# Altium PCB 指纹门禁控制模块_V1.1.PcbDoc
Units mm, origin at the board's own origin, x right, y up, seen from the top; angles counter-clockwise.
Board outline 60 x 20 mm, 2 copper layers (Top Layer, Bottom Layer); 41 components, 29 nets, 157 pads, 102 vias.
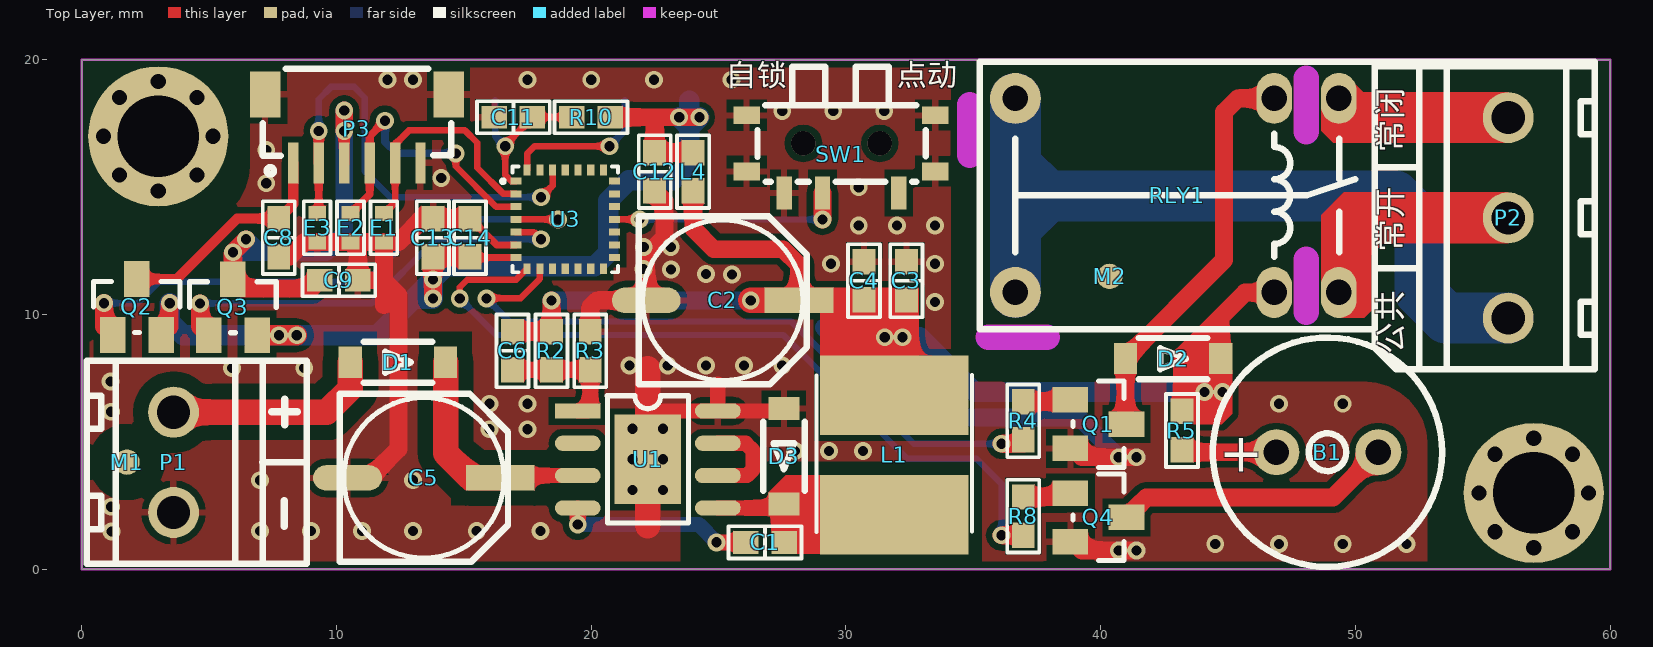
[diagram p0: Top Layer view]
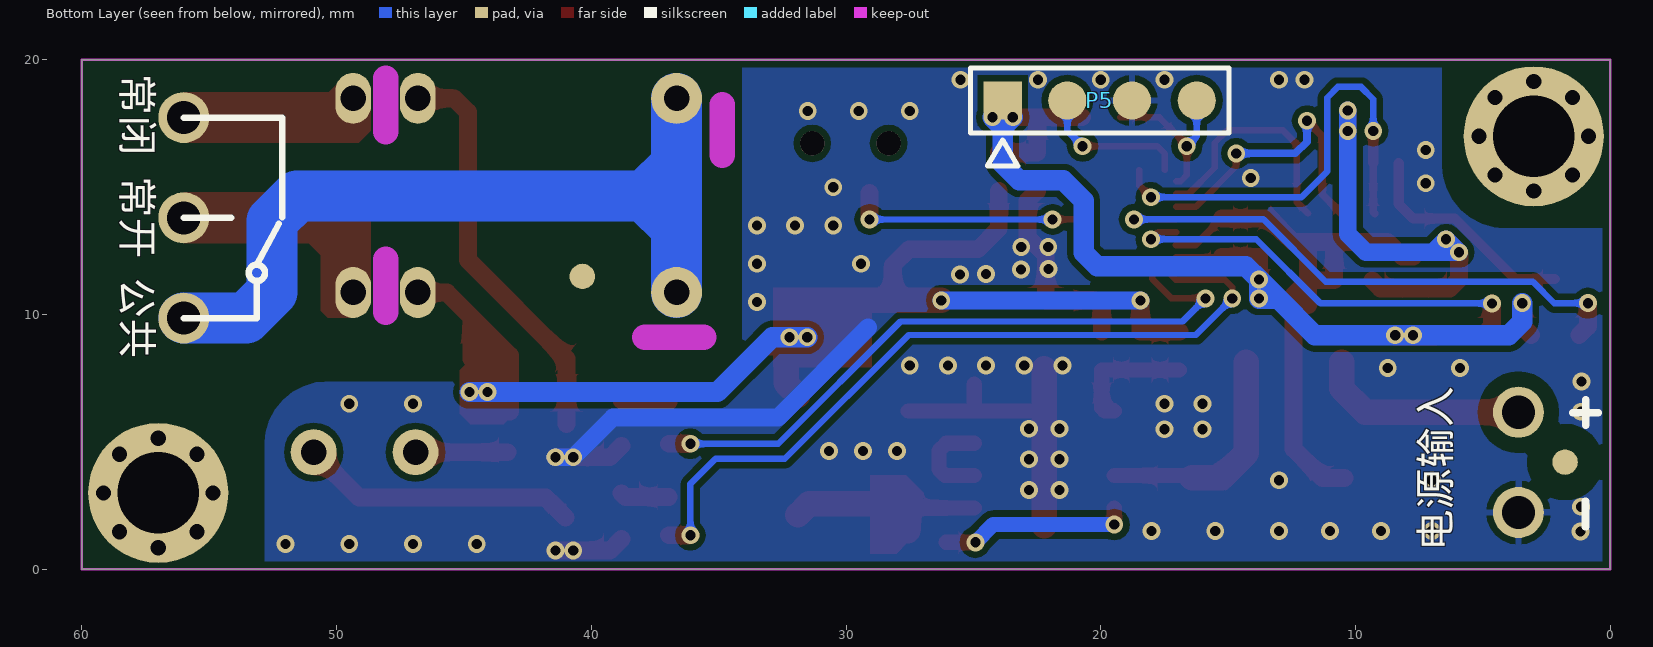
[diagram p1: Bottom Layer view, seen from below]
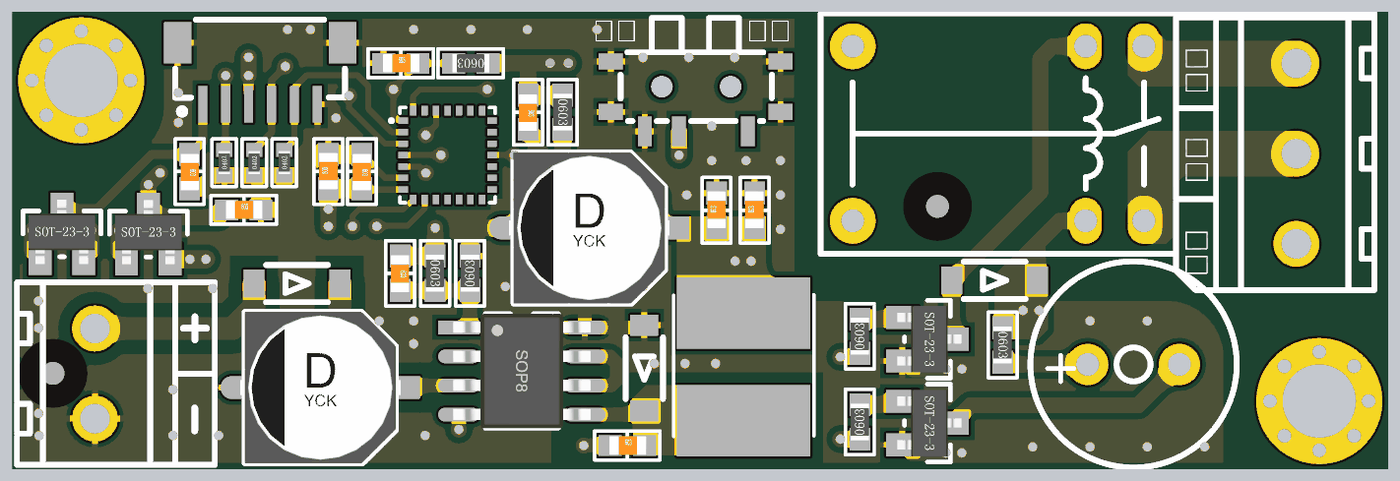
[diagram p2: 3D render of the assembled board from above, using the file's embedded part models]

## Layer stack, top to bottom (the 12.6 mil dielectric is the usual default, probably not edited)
Top Solder: solder mask 0.0102, Solder Resist, Dk 3.5
Top Layer: signal copper 0.0356
Dielectric 1: dielectric 0.32, FR-4, Dk 4.8
Bottom Layer: signal copper 0.0356
Bottom Solder: solder mask 0.0102, Solder Resist, Dk 3.5

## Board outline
0,0 60,0 60,20 0,20

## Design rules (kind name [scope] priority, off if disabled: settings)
Clearance Clearance_2 [InComponent('U3')] p1: gap=0.2
Clearance Clearance_1 [InNet('NetD1_1') Or InNet('VIN') vs InPolygon] p2: gap=0.6
Clearance [All] p3: gap=0.254
ComponentClearance [All] p1: gap=0 collisioncheckmode=3 verticalgap=0 showdistances=FALSE
HoleSize [All] p1 off: absolutevalues=TRUE maxlimit=2.54 minlimit=0.025 maxpercent=80.000 minpercent=20.000
HoleToHoleClearance [All] p1 off: gap=0.254 allowstackedmicrovias=TRUE
LayerPairs [All] p1 off: enforce=TRUE
MinimumSolderMaskSliver [All] p1 off: minsoldermaskwidth=0.254
NetAntennae [All] p1 off: netantennaetolerance=0
PolygonConnect PolygonConnect_1 [InNet('GND') And isvia] p1: connectstyle=Direct reliefconductorwidth=0.254 reliefentries=4 polygonreliefangle="90 Angle" airgapwidth=0.254
PolygonConnect [All] p2: connectstyle=Relief reliefconductorwidth=0.254 reliefentries=4 polygonreliefangle="90 Angle" airgapwidth=0.254
RoutingVias [All] p1: holewidth=0.711 width=1.27 viastyle="Through Hole" minholewidth=0.1 minwidth=0.1 maxholewidth=0.711 maxwidth=1.27
SilkToBoardRegionClearance [All] p1 off:
SilkToSilkClearance [All] p1 off: silktosilkclearance=0.254
SilkToSolderMaskClearance [IsPad] p1 off: minsilkscreentomaskgap=0.254 clearancetoexposedcopper=TRUE
SolderMaskExpansion [All] p1: expansion=0.102
Width [All] p1: maxlimit=8 minlimit=0.254 preferedwidth=0.254
21 further rules are at their usual default settings.

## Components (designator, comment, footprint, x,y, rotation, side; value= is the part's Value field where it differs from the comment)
B1 "QMB-09B-03" BUZZER-9MM 48.9,4.6 r0 top
C1 "104 100V 10% X7R 0603" C0603 26.82,1.06 r0 top
C2 "220uF 6.3V 贴片电解电容" CAP-D6.3XH7.7 25.16,10.56 r0 top
C3 "10uF 10V 20% X5R 0603" C0603 32.37,11.33 r90 top
C4 "104 16V 10% X7R 0603" C0603 30.71,11.33 r90 top
C5 "10uF 100V 贴片电解电容" CAP-D6.3XH7.7 13.43,3.59 r0 top
C6 "104 16V 10% X7R 0603" C0603 16.91,8.58 r270 top
C8 "104 16V 10% X7R 0603" C0603 7.73,13.02 r270 top
C9 "104 16V 10% X7R 0603" C0603 10.09,11.35 r0 top
C11 "104 16V 10% X7R 0603" C0603 16.94,17.75 r0 top
C12 "10uF 10V 20% X5R 0603" C0603 22.49,15.61 r270 top
C13 "10uF 10V 20% X5R 0603" C0603 13.78,13.02 r90 top
C14 "104 16V 10% X7R 0603" C0603 15.24,13.02 r270 top
D1 "SOD1F3" SOD-123 12.41,8.13 r0 top
D2 "SOD1F3" SOD-123 42.84,8.27 r0 top
D3 "SOD1F3" SOD-123 27.56,4.44 r270 top
E1 "LXES15AAA1-153" R0402 11.86,13.41 r90 top
E2 "LXES15AAA1-153" R0402 10.55,13.41 r90 top
E3 "LXES15AAA1-153" R0402 9.24,13.41 r90 top
L1 "33uH" L-SMD-5.8X5.2 31.89,4.49 r90 top
L4 "120Ω @100MHz" R0603 24,15.61 r270 top
M1 "MARK" MARK 1.77,4.21 r0 top
M2 "MARK" MARK 40.35,11.5 r0 top
P1 "KF396-2 接线端子" KF396-2 3.6,4.2 r270 top
P2 "KF396-3 接线端子" KF396-3 56,13.8 r90 top
P3 "6P-1.0mm-立式贴片插座" "SH 1.0_LS_6P" 10.8,17.3 r0 top
P5 "STM8 烧写口" HDR1X4 23.85,18.408 r180 bottom
Q1 "S8050" SOT-23 39.91,5.7 r270 top
Q2 "SI2301" SOT-23 2.16,10.3 r0 top
Q3 "SI2301" SOT-23 5.93,10.29 r0 top
Q4 "S8050" SOT-23 39.91,2.04 r270 top
R2 "154K 1% 0603" R0603 18.435,8.58 r270 top
R3 "10K 1% 0603" R0603 19.96,8.58 r90 top
R4 "1K 1% 0603" R0603 36.96,5.83 r90 top
R5 "51R 1% 0603" R0603 43.19,5.45 r270 top
R8 "1K 1% 0603" R0603 36.96,2.09 r90 top
R10 "10K 1% 0603" R0603 19.99,17.75 r180 top
RLY1 "HK4100F-DC3V-SHG" RELAY-TH_HK4100F-XXX-XXXX 43,14.68 r180 top
SW1 "MSK12CO2-BDM" SW-SMD_MSK12CO2-BDM 29.8,16.3 r180 top
U1 "MP9486A" SOP-8E 22.22,4.315 r270 top
U3 "STM8L151G4U6" UFQFPN-28 18.98,13.74 r270 top

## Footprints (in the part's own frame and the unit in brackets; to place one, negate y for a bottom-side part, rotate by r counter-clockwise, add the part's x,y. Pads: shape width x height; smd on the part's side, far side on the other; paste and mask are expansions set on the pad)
BUZZER-9MM [mm]
  round 1.8 hole 1: 1(-2,0) 2(2,0)
  silkscreen extent -4.5,-4.5 4.5,4.5
C0603 [mm]
  rect 1x0.9 smd: 1(-0.75,0) 2(0.75,0)
  silkscreen extent -1.43,-0.63 1.43,0.63, body extent -0.78,-0.4 0.82,0.4, height 0.3
CAP-D6.3XH7.7 [mm] "贴片电解电容，直径6.3mm，高7.7mm"
  rect 2.7x1 smd: 1(3,0)
  oval 2.7x1 smd: 2(-3,0)
  silkscreen extent -3.3,-3.3 3.3,3.3, body extent -3.5,-3.3 3.5,3.3, height 7.7
HDR1X4 [mm] "Connector; Header; 4 Position"
  rect 1.5x1.5 smd: 1(0,0)
  round 1.5 smd: 2(2.54,0) 3(5.08,0) 4(7.62,0)
  silkscreen extent -1.27,-1.27 8.89,1.27
KF396-2 [mm]
  round 2 hole 1.3: 1(-1.968,0) 2(1.968,0)
  silkscreen extent -3.98,-3.4 3.98,3.5
KF396-3 [mm]
  round 2 hole 1.3: 1(-3.937,0) 2(0,0) 3(3.937,0)
  silkscreen extent -5.95,-3.4 5.95,3.5
L-SMD-5.8X5.2 [mm]
  rect 3.124x5.82 smd: 1(-2.351,0) 2(2.351,0)
  silkscreen extent -3.03,-3.06 3.15,3.05
MARK [mm] "MARK点，外径3mm，内径1mm"
  round 1 smd: 1(0,0)
  round 1 smd far side: 1(0,0)
  Top Layer pour cut-out: 0,1.5 0.074,1.5 0.294,1.478 0.577,1.393 0.837,1.253 1.066,1.066 1.253,0.837 1.393,0.577 1.478,0.294 1.5,0.074 1.5,0 1.5,0 1.5,0 1.5,-0.074 1.478,-0.294 1.393,-0.577 1.253,-0.837 1.066,-1.066 0.837,-1.253 0.577,-1.393 0.294,-1.478 0.074,-1.5 0,-1.5 0,-1.5 -0.074,-1.5 -0.294,-1.478 -0.577,-1.393 -0.837,-1.253 -1.066,-1.066 -1.253,-0.837 -1.393,-0.577 -1.478,-0.294 -1.5,-0.074 -1.5,0 -1.5,0 -1.5,0 -1.5,0.074 -1.478,0.294 -1.393,0.577 -1.253,0.837 -1.066,1.066 -0.837,1.253 -0.577,1.393 -0.294,1.478 -0.074,1.5 0,1.5
  Bottom Layer pour cut-out: 0,1.5 -0.074,1.5 -0.294,1.478 -0.577,1.393 -0.837,1.253 -1.066,1.066 -1.253,0.837 -1.393,0.577 -1.478,0.294 -1.5,0.074 -1.5,0 -1.5,0 -1.5,0 -1.5,-0.074 -1.478,-0.294 -1.393,-0.577 -1.253,-0.837 -1.066,-1.066 -0.837,-1.253 -0.577,-1.393 -0.294,-1.478 -0.074,-1.5 0,-1.5 0,-1.5 0.074,-1.5 0.294,-1.478 0.577,-1.393 0.837,-1.253 1.066,-1.066 1.253,-0.837 1.393,-0.577 1.478,-0.294 1.5,-0.074 1.5,0 1.5,0 1.5,0 1.5,0.074 1.478,0.294 1.393,0.577 1.253,0.837 1.066,1.066 0.837,1.253 0.577,1.393 0.294,1.478 0.074,1.5 0,1.5
R0402 [mm]
  rect 0.6x0.7 smd: 1(-0.56,0) 2(0.56,0)
  silkscreen extent -1.04,-0.52 1.04,0.53, body extent -0.5,-0.25 0.5,0.25, height 0.35
R0603 [mm]
  rect 1x0.9 smd: 1(-0.75,0) 2(0.75,0)
  silkscreen extent -1.43,-0.63 1.43,0.63, body extent -0.8,-0.4 0.8,0.4, height 0.45
RELAY-TH_HK4100F-XXX-XXXX [mm]
  oval 1.4x2 hole 1: 1(-6.35,3.81) 2(-6.35,-3.81) 3(-3.81,3.81) 4(-3.81,-3.81)
  round 2 hole 1: 5(6.35,3.81) 6(6.35,-3.81)
  silkscreen extent -7.75,-5.25 7.75,5.25
"SH 1.0_LS_6P" [mm] "立式，1mm间距插座"
  rect 1.2x1.8 smd: 0(-3.6,1.345) 0(3.6,1.345)
  rect 0.4x1.6 smd: 1(-2.5,-1.345) 2(-1.5,-1.345) 3(-0.5,-1.345) 4(0.5,-1.345) 5(1.5,-1.345) 6(2.5,-1.345)
  silkscreen extent -3.7,-1.8 3.7,2.35
SOD-123 [mm]
  rect 0.909x1.219 smd: 1(-1.87,0) 2(1.87,0)
  silkscreen extent -1.35,-0.81 1.35,0.81
SOP-8E [mm]
  rect 3.51x2.62 smd: 0(0,0)
  rect 0.6x1.8 smd: 1(-1.905,-2.75)
  oval 0.6x1.8 smd: 2(-0.635,-2.75) 3(0.635,-2.75) 4(1.905,-2.75) 5(1.905,2.75) 6(0.635,2.75) 7(-0.635,2.75) 8(-1.905,2.75)
  silkscreen extent -2.5,-1.59 2.5,1.59, body extent -2.5,-3 2.5,3, height 1.9
SOT-23 [mm]
  rect 1x1.4 smd: 1(-0.95,-1.1) 2(0.95,-1.1) 3(0,1.1)
  silkscreen extent -1.7,-1 1.7,1, body extent -1.45,-1.31 1.45,1.49, height 1.2
SW-SMD_MSK12CO2-BDM [mm]
  rect 0.6x1.3 smd: 1(2.225,1.525) 2(0.725,1.525) 3(-2.275,1.525)
  rect 1.05x0.7 smd: 4(-3.7,-1.525) 4(-3.7,0.675) 4(3.7,0.675) 4(3.7,-1.525)
  round 0.95 hole 0.95 unplated: ""(-1.525,-0.425) ""(1.475,-0.425)
  silkscreen extent -3.33,-3.42 3.27,1.08
UFQFPN-28 [mm]
  rect 0.28x0.425 smd: 1(-1.5,-1.938) 2(-1,-1.938) 3(-0.5,-1.938) 4(0,-1.938) 5(0.5,-1.938) 6(1,-1.938) 7(1.5,-1.938) 15(1.5,1.938) 16(1,1.938) 17(0.5,1.938) 18(0,1.938) 19(-0.5,1.938) 20(-1,1.938) 21(-1.5,1.938)
  rect 0.425x0.28 smd: 8(1.938,-1.5) 9(1.938,-1) 10(1.938,-0.5) 11(1.938,0) 12(1.938,0.5) 13(1.938,1) 14(1.938,1.5) 22(-1.938,1.5) 23(-1.938,1) 24(-1.938,0.5) 25(-1.938,0) 26(-1.938,-0.5) 27(-1.938,-1) 28(-1.938,-1.5)
  silkscreen extent -2.08,-2.52 2.08,2.08

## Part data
C1 C3 C4 C6 C8 C9 C11 C12 C13 C14: library part CapN, "CAP"
C2 C5: library part CapH, "100uF,35V,插件电解电容"
D1 D2 D3: library part 1N4007
L1: library part InductorDM, "GCD54-330MC"
L4: library part Inductor, "CBW160808U121T"
P1: library part "Header 2", "Header, 2-Pin"
P2: library part "Header 3", "Header, 3-Pin"
P3: library part "Header 6", "Header, 6-Pin"
P5: library part "Header 4", "Header, 4-Pin"
Q1 Q4: library part NPN, "NPN晶体管"
Q2 Q3: library part MOSFET-P
R2 R3 R4 R5 R8 R10: library part Res1, "Resistor"
U1: "100V 输入，3.5A 峰值电流限 降压转换器"

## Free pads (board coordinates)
  round 0.7 hole 0.6: 0(0.85,17) 0(1.48,15.48) 0(1.48,18.52) 0(3,14.85) 0(3,19.15) 0(4.52,15.48) 0(4.52,18.52) 0(5.15,17) 0(54.85,3) 0(55.48,1.48) 0(55.48,4.52) 0(57,0.85) 0(57,5.15) 0(58.52,1.48) 0(58.52,4.52) 0(59.15,3)
  round 5.5 hole 3.2: 0(3,17) 0(57,3)

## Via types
v1: diameter 0.7, hole 0.4, Top Layer to Bottom Layer, tented both sides, 102 vias

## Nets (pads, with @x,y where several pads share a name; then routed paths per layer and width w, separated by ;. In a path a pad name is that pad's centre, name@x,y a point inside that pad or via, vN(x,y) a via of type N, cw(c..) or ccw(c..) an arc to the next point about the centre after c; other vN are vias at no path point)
3V3: C2.1 C3.1 C4.1 C6.1 D2.2 L1.2 L4.2 R2.1 R5.1 RLY1.3 | length 52.5
  Top Layer w0.7: C6.1 R2.1 18.44,9.335 v1(18.44,10.56) ; L4.2 24,13.38 24.81,12.57 27.53,12.57 28.16,11.94 C2.1 ; R5.1 43.19,7.99 ; RLY1.3 45.67,10.87 44.71,9.91 ; 43.19,7.99 43.19,8.39 44.71,9.91 ; 43.19,7.99 43.47,8.27 D2.2 44.71,9.91
  Top Layer w1: v1(26.26,10.56) C2.1 32.35,10.56 32.35,7.301 L1.2
  Bottom Layer w0.7: v1(18.44,10.56) v1(26.26,10.56)
  Bottom Layer w0.8: v1(31.52,9.11) 32.9,9.11 35.05,6.96 v1(44.08,6.96) v1(44.78,6.96)
  other v1: 32.22,9.11
BEEP: R8.1 U3.8 | length 30.5
  Top Layer w0.254: v1@14.835,10.65 14.835,11.075 15.13,11.37 17.048,11.37 U3.8
  Top Layer w0.7: v1(36.11,1.34) R8.1
  Bottom Layer w0.254: v1(14.835,10.63) 16.265,9.2 27.54,9.2 32.4,4.34 35.12,4.34 36.11,3.35 v1(36.11,1.34)
F_INT: E3.2 P3.2 U3.26 | length 18.2
  Top Layer w0.254: v1(18.03,14.61) 18.48,15.06 U3.26
  Top Layer w0.3: E3.2 9.3,14.03 P3.2
  Top Layer w0.4: P3.2 v1(9.3,17.21)
  Bottom Layer w0.254: v1(9.3,17.21) 9.3,18.46 9.78,18.94 10.69,18.94 11.11,18.52 11.11,15.62 12.12,14.61 v1(18.03,14.61)
F_RXD: E1.2 P3.5 U3.2 | length 9.5
  Top Layer w0.254: E1.2 12.3,14.41 P3.5 12.3,16.69 12.84,17.23 15.04,17.23 15.52,16.75 15.52,15.77 16.55,14.74 U3.2
F_TXD: E2.2 P3.4 U3.3 | length 11.5
  Top Layer w0.254: v1(14.68,16.33) 14.68,15.82 16.26,14.24 U3.3
  Top Layer w0.3: E2.2 11.3,14.72 P3.4 11.3,17.01 v1(11.9,17.61)
  Bottom Layer w0.3: v1(11.9,17.61) 11.9,16.79 12.36,16.33 v1(14.68,16.33)
FM_3V3: C9.1 P3.3 Q3.3 | length 18.5
  Top Layer w0.4: P3.3 v1(10.3,17.21)
  Top Layer w0.7: v1(6.44,12.96) v1(5.93,12.45) Q3.3 6.3,11.02 9.01,11.02 C9.1 ; v1(10.3,17.21) v1(10.3,18.01)
  Bottom Layer w0.7: v1(10.3,18.01) 10.3,13.17 9.58,12.45 6.95,12.45 ; 6.95,12.45 v1(5.93,12.45) v1(6.44,12.96) 6.95,12.45
FM_EN: Q3.1 U3.5 | length 16.9
  Top Layer w0.254: U3.5 17.75,13.24 v1(18.03,12.96)
  Top Layer w0.7: v1(4.64,10.44) 4.64,9.53 Q3.1
  Bottom Layer w0.254: v1(4.64,10.44) 11.37,10.44 13.89,12.96 v1(18.03,12.96)
FT_3V3: C8.1 P3.1 Q2.3 | length 9
  Top Layer w0.4: Q2.3 3.72,11.4 6.09,13.77 C8.1 8.3,14.34 P3.1
FT_EN: Q2.1 U3.4 | length 22.2
  Top Layer w0.254: U3.4 v1(18.69,13.74)
  Top Layer w0.7: v1(0.87,10.45) 0.87,9.54 Q2.1
  Bottom Layer w0.254: v1(0.87,10.45) 2.19,10.45 3.03,11.29 11.16,11.29 13.61,13.74 v1(18.69,13.74)
GND: C2.2 C3.2 C4.2 C5.2 C8.2 C9.2 C11.1 C12.2 C13.2 C14.1 D3.1 E1.1 E2.1 E3.1 P1.2 P3.0 P3.6 P5.3 Q1.2 Q4.2 R3.2 SW1.1 SW1.4 U1.0 U1.8 U3.6 | length 65.3
  Top Layer w0.28: C14.1 15.25,13.77 16.28,12.74 U3.6
  Top Layer w0.6: 22.22,6.22 U1.8 ; 24.97,7.27 U1.8 ; D3.1@27.56,6.22 U1.8
  Top Layer w0.7: C8.2 8.16,12.27 8.74,12.85 E1.1 ; C5.2 11.29,3.59 12.43,4.73 12.43,10.75 11.86,11.32 ; E2.1 10.84,12.56 C9.2 11.83,11.35 11.86,11.32 ; 11.86,10.37 11.86,11.32 ; C14.1 C13.2 13.36,13.77 12.44,12.85 E1.1 ; R3.2 19.96,10.3 20.22,10.56 C2.2 22.16,12.33 22.88,13.05 22.88,14.47 C12.2 ; Q4.2@38.81,1.19 39.26,0.74 v1(41.41,0.74) ; Q1.2@38.81,4.85 39.26,4.4 v1(40.71,4.4) v1(41.41,4.4) ; 11.86,11.32 E1.1
  Top Layer w1: 22.22,1.72 U1.0 22.22,6.22 22.22,7.87
  Bottom Layer w0.7: 29.132,9.492 32.668,5.956 39.154,5.956 v1(40.71,4.4) v1(41.41,4.4)
  other v1: 40.71,0.74 44.5,1 47,1 49.5,1 52,1 1.16,1.49 7,1.5 9,1.5 11,1.5 13,1.5 15.5,1.5 18,1.5 1.14,2.46 21.62,3.12 22.82,3.12 7,3.5 13,3.5 21.62,4.32 22.82,4.32 28,4.64 29.335,4.64 30.67,4.64 16,5.5 17.5,5.5 21.62,5.52 22.82,5.52 1.14,6.19 16,6.5 17.5,6.5 47,6.5 49.5,6.5 1.13,7.37 5.9,7.91 8.73,7.91 21.5,8 23,8 24.5,8 26,8 27.5,8 33.5,10.5 25.52,11.58 24.5,11.6 23.13,11.77 22.05,11.79 29.41,12 33.5,12 22.06,12.65 23.12,12.65 30.5,13.5 32,13.5 33.5,13.5 30.5,15 7.24,15.16 14.11,15.36 7.24,16.46 27.5,18 29.5,18 31.5,18 12,19.22 13,19.22 17.5,19.22 20,19.22 22.46,19.22 25.5,19.22
M_3V3: C12.1 C13.1 C14.2 L4.1 P5.1 Q2.2 Q3.2 R10.1 U3.7 | length 44.6
  Top Layer w0.28: C14.2 15.27,12.24 U3.7
  Top Layer w0.7: Q2.2 3.45,9.54 v1(3.45,10.45) ; v1@13.78,10.68 C13.1 C14.2 ; R10.1 v1(23.45,17.75) v1(24.25,17.75) ; 22.49,17.73 C12.1 L4.1
  Top Layer w0.8: Q3.2 v1(7.74,9.19) v1(8.44,9.19)
  Bottom Layer w0.8: v1(3.45,10.45) 3.45,9.72 3.98,9.19 v1(7.74,9.19) v1(8.44,9.19) 11.59,9.19 13.08,10.68 ; v1(23.45,17.75) 23.85,17.35 ; P5.1 23.85,17.35 ; v1(24.25,17.75) 23.85,17.35 ; 13.08,10.68 13.13,10.63 v1(13.78,10.63) v1(13.78,11.38) ; 13.08,10.68 v1(13.78,11.38) ; v1(13.78,11.38) 14.3,11.9 20.14,11.9 20.67,12.43 20.67,14.47 21.47,15.27 23.2,15.27 23.85,15.92 23.85,17.35
NetB1_1: B1.1 R5.2 | length 3.6
  Top Layer w0.7: R5.2@43.29,4.6 B1.1
NetB1_2: B1.2 Q4.3 | length 11
  Top Layer w0.7: Q4.3 41.79,2.82 49.12,2.82 B1.2
NetC1_1: C1.1 U1.4 | length 7.5
  Top Layer w0.6: v1(19.47,1.76) U1.4 ; v1(24.92,1.06) C1.1
  Bottom Layer w0.6: v1(19.47,1.76) 24.22,1.76 v1(24.92,1.06)
NetC1_2: C1.2 D3.2 L1.1 U1.5 | length 7.9
  Top Layer w0.6: U1.5 D3.2@27.4,2.41
  Top Layer w1: D3.2@27.4,2.41 27.57,2.24 27.57,1.52 ; D3.2 31.459,2.57 L1.1
NetC6_2: C6.2 R2.2 R3.1 U1.1 | length 5.1
  Top Layer w0.6: C6.2 R2.2 R3.1 19.96,6.33 19.85,6.22 U1.1
NetD1_1: D1.1 P1.1 | length 8.4
  Top Layer w1: P1.1 9.608,6.168 10.54,7.1 D1.1
NetD2_1: D2.1 Q1.3 RLY1.4 | length 16
  Top Layer w0.7: Q1.3@40.97,5.7 D2.1 44.84,12.14 44.84,17.95 45.38,18.49 RLY1.4
NetQ1_1: Q1.1 R4.2 | length 1.9
  Top Layer w0.7: R4.2 38.74,6.58 Q1.1
NetQ4_1: Q4.1 R8.2 | length 1.9
  Top Layer w0.7: R8.2 38.66,2.84 Q4.1
NetU1_6: U1.6 U1.7 | length 3.7
  Top Layer w0.6: U1.6 26.11,3.68 26.35,3.92 26.35,4.66 26.06,4.95 U1.7
NRST: C11.2 P5.4 R10.2 U3.1 | length 6.7
  Top Layer w0.254: U3.1 16.862,15.24 16.62,15.482 v1(16.62,16.61) 16.62,16.66 17.69,17.73 C11.2 R10.2
  Bottom Layer w0.254: P5.4 16.23,17 v1(16.62,16.61)
RLY_1: R4.1 U3.9 | length 26.2
  Top Layer w0.254: v1@15.89,10.65 17.23,10.65 17.98,11.4 U3.9
  Top Layer w0.7: v1(36.11,4.93) R4.1@36.96,4.93
  Bottom Layer w0.254: v1(15.89,10.63) 16.79,9.73 27.86,9.73 32.66,4.93 v1(36.11,4.93)
RLY_CLOSE: P2.3 RLY1.2
RLY_COM: P2.1 RLY1.5 RLY1.6 | length 32.9
  Bottom Layer w2: RLY1.5 RLY1.6 ; 36.65,13.4 37.9,14.65 ; 36.65,15.9 37.9,14.65 ; P2.1 53.557,9.863 52.53,10.89 52.53,13.68 51.56,14.65 37.9,14.65
RLY_OPEN: P2.2 RLY1.1
SW_MODE: SW1.2 U3.18 | length 9.2
  Top Layer w0.254: U3.18 21.88,13.74 v1@21.89,13.73
  Top Layer w0.7: v1(29.075,13.735) SW1.2
  Bottom Layer w0.254: v1(21.89,13.735) v1(29.075,13.735)
SWIM: P5.2 U3.28 | length 6
  Top Layer w0.254: U3.28 17.48,16.32 17.77,16.61 v1(20.71,16.61)
  Bottom Layer w0.254: v1(20.71,16.61) 21.31,17.21 P5.2
VIN: C5.1 D1.2 U1.3 | length 9.2
  Top Layer w0.6: C5.1 16.52,3.68 U1.3
  Top Layer w1: D1.2 14.28,4.56 15.25,3.59 C5.1
pads on no net: M1.1 M2.1 SW1. SW1.3 U1.2 U3.10 U3.11 U3.12 U3.13 U3.14 U3.15 U3.16 U3.17 U3.19 U3.20 U3.21 U3.22 U3.23 U3.24 U3.25 U3.27

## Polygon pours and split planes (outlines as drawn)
GND on Top Layer "GND" (solid, remove dead copper, pour order 0): 0,0 0,20 60,20 60,0
GND on Bottom Layer "GND" (solid, remove dead copper, pour order 2): 0,0 0,20 60,20 60,0

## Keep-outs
Keep-Out Layer:
  lines w0.1: 0,0 60,0 60,20 0,20 0,0
  lines w1: 34.85,16.25 34.85,18.25 ; 35.59,9.11 37.9,9.11 ; 48.07,10.09 48.07,12.18 ; 48.07,17.18 48.07,19.29

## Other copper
Top Layer:
  rectangle net 3V3: 28.98,7.92 32.86,11.06
  pour cut-out: 35.35,4.26 35.35,0 23.5,0 23.5,4.25 35.34,4.25
  region net 3V3: 43.19,6.2 43.19,8.39 44.71,9.91 44.71,8.27 45.17,7.81 45.17,6.11 44.76,5.7 43.43,5.7 43.22,5.91
  region net NetC1_2: 27.57,1.06 28.01,0.62 29.04,0.62 29.04,3.69 29.03,3.7 27.64,3.7 26.97,3.03 26.97,2.79 27.52,2.24 27.57,2.24
  region net RLY_CLOSE: 49.35,18.41 48.65,18.41 48.65,17.21 49.12,16.74 56,16.74 56,18.73 50.31,18.73 49.81,19.23 49.35,18.77
  region net RLY_OPEN: 49.35,10.79 48.65,10.79 48.65,13.91 49.54,14.8 56,14.8 56,12.81 51.09,12.81 50.62,12.34 50.62,10.15 50.34,9.87 49.35,9.87
  pour cut-out: 0,19.99 6.61,19.99 6.61,15.93 cw(c4.07,15.93) 4.07,13.39 0,13.39
  pour cut-out: 60,20 34.11,20 34.11,7.37 50.34,7.37 cw(c50.34,4.89) 52.82,4.89 52.82,0 60,0
Bottom Layer:
  pour cut-out: 0,19.99 6.61,19.99 6.61,15.93 cw(c4.07,15.93) 4.07,13.39 0,13.39
  pour cut-out: 60,20.002 34.08,20.002 34.08,7.372 50.34,7.372 cw(c50.34,4.892) 52.82,4.892 52.82,0.002 60,0.002

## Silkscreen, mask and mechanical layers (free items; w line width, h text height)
Top Overlay:
  lines w0.254: 7.09,4.2 8.82,4.2 ; 7.1,0.219 8.83,0.219 8.83,8.182 7.1,8.182 ; 27.889,18.225 27.889,19.725 29.189,19.725 29.189,18.225 ; 50.75,11.817 52.5,11.817 ; 50.75,15.783 52.5,15.783 ; 50.75,19.93 59.4,19.93 59.4,19.75 ; 52.5,7.85 51.61,7.85 50.75,8.71 50.75,19.75 52.5,19.75
  lines w0.3: 7.46,6.18 8.46,6.18 ; 7.95,1.699 7.95,2.699 ; 7.96,5.68 7.96,6.68
  text "自锁" at 25.3,18.7 h1.5
  text "点动" at 32,18.7 h1.5
  text "常闭" at 52.14,16.37 h1.6 r90
  text "常开" at 52.14,12.47 h1.6 r90
  text "公共" at 52.136,8.42 h1.6 r90
Bottom Overlay:
  circle w0.254: c53.13,11.641 r0.321
  lines w0.2: 23.25,15.83 23.85,16.85 24.45,15.83 23.25,15.83
  lines w0.254: 52.13,13.82 52.13,17.735 56,17.735 ; 52.27,13.56 53.13,11.96 ; 53.13,11.32 53.13,9.863 56,9.863 ; 54.13,13.8 56,13.8
  lines w0.3: 0.46,6.15 1.46,6.15 ; 0.96,5.65 0.96,6.65 ; 0.97,1.669 0.97,2.669
  text "常闭" at 58.77,19.44 h2 r90
  text "常开" at 58.77,15.41 h2 r90
  text "公共" at 58.766,11.47 h2 r90
  text "电源输入" at 5.91,0.75 h2 r270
